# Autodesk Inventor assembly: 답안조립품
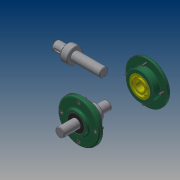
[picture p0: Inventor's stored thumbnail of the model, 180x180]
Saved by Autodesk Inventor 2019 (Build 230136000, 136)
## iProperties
Created: 2019-03
Part Number: 답안조립품
Material: 일반
Document SubType Name: Assembly
Designer: PC312-02
Author: PC312-02
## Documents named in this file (10)
- C:\Users\PC312-02\Desktop\490314V1013\답안조립품.iam
- C:\Users\PC312-02\Desktop\490314V1013\본체.ipt
- C:\Users\PC312-02\Desktop\490314V1013\커버.ipt
- C:\Users\PC312-02\Desktop\490314V1013\볼트 M4.ipt
- 볼트 M4.ipt
- C:\Users\PC312-02\Desktop\490314V1013\오일 실.ipt
- 오일 실.ipt
- C:\Users\PC312-02\Desktop\490314V1013\베어링 6203.ipt
- C:\Users\PC312-02\Desktop\490314V1013\메인 축.ipt
- 메인 축.ipt
